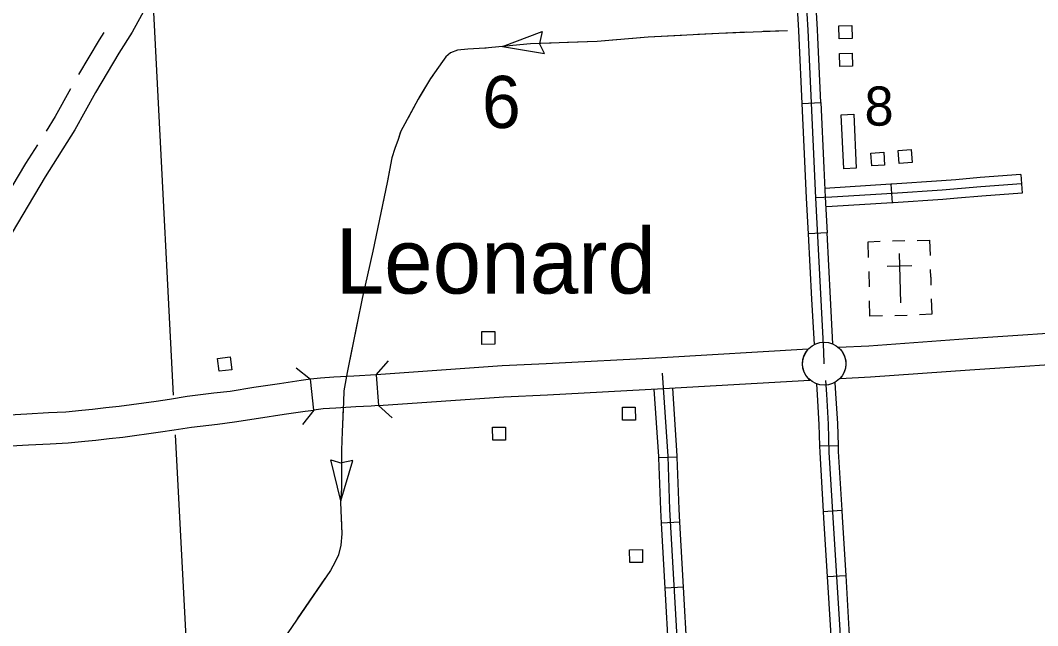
# Model space of a CAD drawing. Extents: x -0.3 to 2.65, y 0 to 1.9.
# Drawn here: x 0.8619 to 0.9604, y 0.404 to 0.4627 of the extents above; entities that cross this region are included whole.
import ezdxf

# ---------------------------------------------------------------- set-up
doc = ezdxf.new("R2010")
doc.units = 0
for name, color, linetype in [('Level 11', 7, 'Continuous'), ('Level 12', 7, 'Continuous'), ('Level 13', 7, 'Continuous'), ('Level 15', 7, 'Continuous'), ('Level 18', 7, 'Continuous'), ('Level 19', 7, 'Continuous'), ('Level 20', 7, 'Continuous'), ('Level 21', 7, 'Continuous'), ('Level 24', 7, 'Continuous'), ('Level 30', 7, 'Continuous'), ('Level 32', 7, 'Continuous')]:
    doc.layers.add(name, color=color, linetype=linetype)

msp = doc.modelspace()

# ---------------------------------------------------------------- linework, layer by layer
at = {"layer": 'Level 11'}
for points in [[(0.873567, 0.487992), (0.876734, 0.426363)], [(0.876934, 0.422539), (0.878421, 0.394316)]]:
    msp.add_lwpolyline(points, dxfattribs=at)
at = {"layer": 'Level 12'}
for p, q in [((0.908622, 0.460118), (0.912461, 0.461576)), ((0.912461, 0.461576), (0.912205, 0.460406)), ((0.908622, 0.460118), (0.912676, 0.459461)), ((0.912676, 0.459461), (0.912205, 0.460406)), ((0.892018, 0.420117), (0.89306, 0.419786)), ((0.892959, 0.41612), (0.892018, 0.420117)), ((0.892959, 0.41612), (0.894143, 0.420052)), ((0.894143, 0.420052), (0.893076, 0.419819))]:
    msp.add_line(p, q, dxfattribs=at)
for points in [[(0.874386, 0.464445), (0.872757, 0.461513), (0.871472, 0.459491), (0.869216, 0.455666), (0.867209, 0.452061), (0.864356, 0.447512), (0.859467, 0.439348)], [(0.87002, 0.46147), (0.869574, 0.460767), (0.86759, 0.457403)], [(0.936215, 0.461655), (0.929568, 0.46139), (0.922744, 0.461032), (0.917784, 0.460621), (0.911324, 0.460372), (0.9069, 0.459955), (0.905278, 0.45988), (0.904265, 0.459777), (0.90359, 0.459498), (0.903135, 0.459131), (0.902808, 0.458661), (0.901656, 0.457012), (0.900464, 0.45502), (0.898753, 0.451871), (0.898512, 0.451116), (0.898194, 0.450262), (0.897926, 0.449334), (0.897469, 0.446953), (0.89606, 0.440307), (0.895032, 0.435716), (0.893594, 0.428553), (0.893268, 0.426784), (0.893218, 0.425709), (0.893151, 0.42351), (0.893106, 0.422846), (0.893045, 0.421051), (0.893049, 0.418258), (0.893045, 0.417347), (0.892948, 0.415959), (0.893059, 0.412949), (0.892977, 0.411828), (0.892755, 0.410905), (0.892437, 0.410243), (0.89196, 0.409404), (0.88379, 0.397403)], [(0.925959, 0.461201), (0.922744, 0.461032), (0.92123, 0.460907)], [(0.93227, 0.461498), (0.929568, 0.46139), (0.927536, 0.461283)], [(0.936215, 0.461655), (0.933848, 0.461561)], [(0.907049, 0.459969), (0.9069, 0.459955), (0.905278, 0.45988), (0.904265, 0.459777), (0.90359, 0.459498), (0.903135, 0.459131), (0.902808, 0.458661), (0.902775, 0.458612)], [(0.913347, 0.46045), (0.911324, 0.460372), (0.908622, 0.460118)], [(0.919656, 0.460776), (0.917784, 0.460621), (0.914926, 0.460511)], [(0.90187, 0.457318), (0.901656, 0.457012), (0.900631, 0.455299)], [(0.86681, 0.456029), (0.865311, 0.453337), (0.86443, 0.451933)], [(0.900631, 0.455299), (0.900464, 0.45502), (0.899488, 0.453224)], [(0.898741, 0.451833), (0.898512, 0.451116), (0.898194, 0.450262), (0.897926, 0.449334), (0.897529, 0.447263)], [(0.863591, 0.450595), (0.862457, 0.448788), (0.861119, 0.446553)], [(0.897207, 0.445717), (0.896224, 0.441081)], [(0.894559, 0.433361), (0.893626, 0.428715)], [(0.893201, 0.425156), (0.893151, 0.42351), (0.893106, 0.422846), (0.893092, 0.422434)], [(0.893045, 0.420855), (0.893048, 0.418486)], [(0.893048, 0.418486), (0.893049, 0.418258), (0.893045, 0.417347), (0.892959, 0.41612)], [(0.893, 0.414542), (0.893059, 0.412949), (0.892977, 0.411828), (0.892755, 0.410905), (0.892437, 0.410243), (0.89227, 0.40995)], [(0.891424, 0.408617), (0.888757, 0.4047)]]:
    msp.add_lwpolyline(points, dxfattribs=at)
at = {"layer": 'Level 13'}
for p, q in [((0.95882, 0.447714), (0.958951, 0.445924)), ((0.946228, 0.446783), (0.94634, 0.444992))]:
    msp.add_line(p, q, dxfattribs=at)
for points in [[(0.95251, 0.447226), (0.951133, 0.447109), (0.946334, 0.44679), (0.946228, 0.446783)], [(0.95882, 0.447714), (0.95488, 0.447428), (0.95251, 0.447226)], [(0.958885, 0.446819), (0.954951, 0.446533), (0.951201, 0.446214), (0.946392, 0.445894), (0.940497, 0.445524), (0.938967, 0.445482)], [(0.946228, 0.446783), (0.939824, 0.446381)], [(0.952663, 0.445438), (0.951269, 0.445319), (0.94645, 0.444999), (0.94634, 0.444992)], [(0.958951, 0.445924), (0.955021, 0.445639), (0.952663, 0.445438)], [(0.94634, 0.444992), (0.940537, 0.444627), (0.940002, 0.444613)]]:
    msp.add_lwpolyline(points, dxfattribs=at)
at = {"layer": 'Level 15'}
for p, q in [((0.939317, 0.421448), (0.941111, 0.421502)), ((0.92555, 0.420375), (0.923756, 0.420309)), ((0.939677, 0.415114), (0.941469, 0.415221)), ((0.925805, 0.414079), (0.924013, 0.413979)), ((0.940059, 0.408806), (0.941851, 0.408915)), ((0.926159, 0.407771), (0.924367, 0.407671))]:
    msp.add_line(p, q, dxfattribs=at)
for points in [[(0.927313, 0.369872), (0.927035, 0.376434), (0.925856, 0.39575), (0.925838, 0.396723), (0.925856, 0.397432), (0.925847, 0.397778), (0.925629, 0.401197), (0.924838, 0.41529), (0.924649, 0.42046), (0.924114, 0.428494)], [(0.939012, 0.427459), (0.93909, 0.426394), (0.939254, 0.423527), (0.939317, 0.421448)], [(0.939888, 0.427784), (0.939985, 0.426452), (0.94015, 0.423566), (0.940233, 0.420861), (0.940612, 0.414511), (0.941272, 0.403626), (0.941516, 0.399268), (0.941906, 0.390681), (0.94249, 0.38177), (0.942947, 0.374207), (0.943386, 0.365305)], [(0.940802, 0.42759), (0.940881, 0.426511), (0.941047, 0.423605), (0.941111, 0.421502)], [(0.923756, 0.420309), (0.923753, 0.420413), (0.923317, 0.426954)], [(0.92555, 0.420375), (0.925545, 0.420506), (0.925109, 0.427055)], [(0.939317, 0.421448), (0.939336, 0.42082), (0.939677, 0.415114)], [(0.941111, 0.421502), (0.941129, 0.420901), (0.941469, 0.415221)], [(0.924013, 0.413979), (0.923941, 0.415249), (0.923756, 0.420309)], [(0.925805, 0.414079), (0.925734, 0.415332), (0.92555, 0.420375)], [(0.939677, 0.415114), (0.939716, 0.414457), (0.940059, 0.408806)], [(0.941469, 0.415221), (0.941508, 0.414565), (0.941851, 0.408915)], [(0.924367, 0.407671), (0.924013, 0.413979)], [(0.926159, 0.407771), (0.925805, 0.414079)], [(0.940059, 0.408806), (0.940376, 0.403574), (0.940436, 0.402504)], [(0.941851, 0.408915), (0.942168, 0.403678), (0.942228, 0.402604)], [(0.926513, 0.401463), (0.926159, 0.407771)], [(0.924721, 0.401362), (0.924367, 0.407671)]]:
    msp.add_lwpolyline(points, dxfattribs=at)
at = {"layer": 'Level 18'}
for p, q in [((0.93765, 0.454612), (0.939443, 0.454694)), ((0.937939, 0.448301), (0.937939, 0.448301)), ((0.940045, 0.442079), (0.938253, 0.441984))]:
    msp.add_line(p, q, dxfattribs=at)
for points in [[(0.939769, 0.429411), (0.939752, 0.430606), (0.938967, 0.445482), (0.938223, 0.461714), (0.937645, 0.471432)], [(0.937361, 0.460924), (0.937327, 0.461666), (0.936996, 0.467219)], [(0.939154, 0.461006), (0.93912, 0.461761), (0.938788, 0.467326)], [(0.939443, 0.454694), (0.939154, 0.461006)], [(0.93765, 0.454612), (0.937361, 0.460924)], [(0.937939, 0.448301), (0.93765, 0.454612)], [(0.939443, 0.454694), (0.939732, 0.448383)], [(0.938253, 0.441984), (0.93807, 0.445438), (0.937939, 0.448301)], [(0.939732, 0.448383), (0.939863, 0.445526), (0.940045, 0.442079)], [(0.938586, 0.435675), (0.938253, 0.441984)], [(0.940378, 0.435769), (0.940045, 0.442079)], [(0.938818, 0.431277), (0.938586, 0.435675)], [(0.940613, 0.431327), (0.940378, 0.435769)]]:
    msp.add_lwpolyline(points, dxfattribs=at)
at = {"layer": 'Level 19'}
for points in [[(0.941224, 0.460878), (0.941196, 0.462123), (0.942445, 0.462152), (0.942473, 0.460906)], [(0.941273, 0.458193), (0.941238, 0.459438), (0.942487, 0.459474), (0.942522, 0.458229)], [(0.941429, 0.453506), (0.942625, 0.453563), (0.942874, 0.448333), (0.941679, 0.448276)], [(0.94704, 0.448802), (0.946946, 0.450044), (0.948192, 0.450138), (0.948285, 0.448896)], [(0.944374, 0.448565), (0.944299, 0.449809), (0.945546, 0.449885), (0.945621, 0.448641)], [(0.907875, 0.432542), (0.907887, 0.431296), (0.906638, 0.431285), (0.906626, 0.43253)], [(0.882275, 0.430065), (0.882424, 0.428829), (0.881183, 0.42868), (0.881035, 0.429916)], [(0.921483, 0.425202), (0.921494, 0.423957), (0.920245, 0.423945), (0.920234, 0.425191)], [(0.90892, 0.423268), (0.908931, 0.422022), (0.907682, 0.422011), (0.907671, 0.423256)], [(0.922177, 0.411411), (0.922188, 0.410166), (0.920939, 0.410154), (0.920928, 0.4114)]]:
    msp.add_lwpolyline(points, close=True, dxfattribs=at)
at = {"layer": 'Level 21'}
for points in [[(0.966227, 0.432655), (0.953679, 0.431806), (0.944084, 0.431124), (0.941158, 0.430978), (0.94135, 0.430794), (0.941527, 0.43058), (0.941749, 0.430114), (0.94186, 0.429701), (0.941867, 0.429339), (0.94183, 0.428977), (0.941705, 0.428615), (0.94152, 0.428238), (0.941307, 0.42799)], [(0.938218, 0.430819), (0.924057, 0.42999), (0.912839, 0.429385), (0.908586, 0.429194), (0.896402, 0.428346)], [(0.896402, 0.428346), (0.89661, 0.425362), (0.908757, 0.426207), (0.912987, 0.426397), (0.924225, 0.427003), (0.938393, 0.427832), (0.938183, 0.428046), (0.937991, 0.428305), (0.937843, 0.428586), (0.937733, 0.428947), (0.937681, 0.429287), (0.937688, 0.429679), (0.937784, 0.430092), (0.937947, 0.430447), (0.938218, 0.430819)], [(0.941307, 0.42799), (0.944264, 0.428138), (0.953886, 0.428821), (0.966438, 0.429671), (0.969745, 0.429913), (0.971631, 0.429977), (0.973234, 0.430025), (0.975922, 0.43009), (0.978927, 0.430204), (0.980326, 0.430204), (0.983746, 0.430334), (0.985788, 0.43035), (0.987692, 0.43045), (0.989003, 0.43052), (0.990451, 0.430618), (0.991487, 0.430696), (0.993497, 0.430865), (0.99513, 0.430963), (0.997256, 0.431096), (0.998874, 0.431228), (1.000856, 0.431358)], [(0.890375, 0.424926), (0.890045, 0.427899), (0.889117, 0.427796), (0.887034, 0.427474), (0.884557, 0.427109), (0.882269, 0.426735), (0.880667, 0.426543), (0.878081, 0.426232), (0.876386, 0.425949), (0.875096, 0.425761), (0.871519, 0.425255), (0.870218, 0.425137), (0.868936, 0.424975), (0.8679, 0.424887), (0.866336, 0.424729), (0.86466, 0.424649), (0.862563, 0.42453), (0.854016, 0.424048), (0.849648, 0.423896)], [(0.896402, 0.428346), (0.894239, 0.428209), (0.892284, 0.428101), (0.890989, 0.428004), (0.890045, 0.427899)], [(0.849648, 0.423896), (0.849752, 0.420906), (0.854152, 0.42106), (0.862732, 0.421543), (0.864816, 0.421661), (0.866559, 0.421745), (0.868177, 0.421909), (0.869249, 0.422), (0.870541, 0.422162), (0.871864, 0.422282), (0.875522, 0.4228), (0.876849, 0.422994), (0.878506, 0.42327), (0.881025, 0.423572), (0.882689, 0.423773), (0.885017, 0.424153), (0.88748, 0.424516), (0.88951, 0.42483), (0.890375, 0.424926)], [(0.89661, 0.425362), (0.895909, 0.425313), (0.894411, 0.425223), (0.892478, 0.425115), (0.891265, 0.425025), (0.890375, 0.424926)]]:
    msp.add_lwpolyline(points, dxfattribs=at)
at = {"layer": 'Level 24'}
msp.add_circle((0.939769, 0.429411), 0.002094, dxfattribs=at)
at = {"layer": 'Level 30'}
for points in [[(0.896406, 0.428346), (0.897588, 0.429697)], [(0.888643, 0.42902), (0.890045, 0.427899)], [(0.890375, 0.424926), (0.889254, 0.423524)], [(0.897957, 0.42418), (0.896606, 0.425361)]]:
    msp.add_lwpolyline(points, dxfattribs=at)
at = {"layer": 'Level 32'}
for p, q in [((0.947591, 0.441298), (0.946395, 0.441263)), ((0.947022, 0.440084), (0.947161, 0.4353)), ((0.944079, 0.438342), (0.944123, 0.436847)), ((0.94586, 0.438853), (0.948263, 0.438923)), ((0.950081, 0.437779), (0.95006, 0.438516)), ((0.947091, 0.437692), (0.947091, 0.437692)), ((0.947091, 0.437692), (0.947091, 0.437692)), ((0.950081, 0.437779), (0.950104, 0.437021)), ((0.946604, 0.434087), (0.9478, 0.434121))]:
    msp.add_line(p, q, dxfattribs=at)
for points in [[(0.948781, 0.441333), (0.949977, 0.441368), (0.950021, 0.439872)], [(0.945193, 0.441228), (0.943996, 0.441193), (0.94404, 0.439698)], [(0.945402, 0.434051), (0.944205, 0.434017), (0.944162, 0.435512)], [(0.950142, 0.435686), (0.950186, 0.434191), (0.94899, 0.434156)]]:
    msp.add_lwpolyline(points, dxfattribs=at)

# ---------------------------------------------------------------- texts
at = {"layer": 'Level 19'}
msp.add_text('8', height=0.003791, dxfattribs=at).set_placement((0.943673, 0.45246))
at = {"layer": 'Level 20'}
msp.add_text('6', height=0.00505, dxfattribs=at).set_placement((0.906637, 0.452232))
at = {"layer": 'Level 24'}
msp.add_text('Leonard', height=0.0063181, dxfattribs=at).set_placement((0.892464, 0.436204))

doc.saveas('drawing.dxf')
